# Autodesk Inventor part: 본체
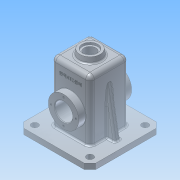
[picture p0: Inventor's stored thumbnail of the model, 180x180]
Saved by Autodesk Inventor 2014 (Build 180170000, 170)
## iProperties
Created: 2016-02
Part Number: 본체
Material: 알루미늄 6061
Document SubType Name: Modeling
Designer: net
Density: 2.71 g/cm^3
Appearance: 알루미늄 - 평지
Mass: 932.811 g
Surface Area: 1043.48 cm^2
Volume: 344.211 cm^3
Author: net
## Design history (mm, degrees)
sketch "스케치1"
  geometry: C1 r 27.5 at (0, 0); 1 further point
  constraints: 1 centre point, 1 coincident
  dimensions: "d0" = 55 diameter of C1
extrude "돌출1" new body sketch "스케치1" stored distance "d1" = 96; taper "d2" = 0 deg
sketch "스케치2"
  geometry: L1 (-35, 65)-(35, 65); L2 (35, 65)-(35, -55); L3 (35, -55)-(-35, -55); L4 (-35, -55)-(-35, 65); 2 further points
  constraints: 8 end point, 2 parallel, 1 horizontal, 1 midpoint, 1 perpendicular, 1 vertical alignment
  dimensions: "d3" = 70 distance of L1.start L1.end; "d4" = 120 distance of L1.end L2.end; "d5" = 55 distance from line of point (0, 0) L3
extrude "돌출2" join sketch "스케치2" stored distance "d6" = 70; taper "d7" = 0 deg
sketch "스케치3"
  geometry: L1 (-30, 30)-(100, 30); L2 (100, 30)-(100, -100); L3 (100, -100)-(-30, -100); L4 (-30, -100)-(-30, 30); 3 further points
  constraints: 8 end point, 2 midpoint, 2 parallel, 1 horizontal, 1 horizontal alignment, 1 perpendicular, 1 vertical alignment
  dimensions: "d8" = 130 distance of L1.start L1.end; "d9" = 130 distance of L1.end L2.end
extrude "돌출3" join sketch "스케치3" distance "d10" = 10; taper "d11" = 0 deg
sketch "스케치5"
  geometry: L1 (-35, 65)-(35, 65) reference; L2 (65, -55)-(-65, -55) reference; L3 (-35, -45)-(-35, 65) reference; L4 (35, 65)-(35, -45) reference; L5 (-30, 60)-(30, 60); L6 (30, 60)-(30, -55); L7 (-30, -55)-(-30, 60); 1 further point
  constraints: 6 end point, 3 parallel, 2 point on line
  dimensions: "d12" = 5 distance between parallel lines of L4 L6; "d13" = 5 distance between parallel lines of L1 L5; "d14" = 5 distance between parallel lines of L3 L7
extrude "돌출4" cut sketch "스케치5" stored distance "d15" = 60; taper "d16" = 0 deg
sketch "스케치6"
  geometry: L1 (-30, 60)-(-30, -55) reference; L2 (0, 0)-(-30, 0); L3 (-30, 27.5)-(-23, 20.5); L4 (-23, 20.5)-(-23, 0); L5 (-35, 65)-(-35, -45) reference
  constraints: 6 end point, 3 point on line, 2 perpendicular
  dimensions: "d17" = 135 deg angle of L3 L4; "d18" = 12 distance between parallel lines of L5 L4; "d19" = 55 diameter of L3.start L2
revolve "회전1" sketch "스케치6" stored, may be unused: angle "d20" = 90 deg
sketch "스케치7"
  geometry: C1 r 20.5 at (0, 0) reference; C2 r 16 at (0, 0)
  constraints: 1 centre point, 1 coincident
  dimensions: "d21" = 32 diameter of C2
extrude "돌출5" cut sketch "스케치7" stored distance "d22" = 60; taper "d23" = 0 deg
sketch "스케치8" dims "d24" = 45
  geometry: C1 r 16 at (0, 0) reference; C2 r 27.5 at (0, 0) reference; 2 further points
  constraints: 2 vertical alignment, 1 coincident, 2 other
hole "구멍1" sketch "스케치8" at (0, 22.5) diameter "d25" = 3.242; stored, may be unused: countersink angle "d29" = 90 deg, drill point angle "d31" = 118 deg; dims "d26" = 8, "d27" = 4, "d28" = 2, "d30" = 10
sketch "스케치9" dims "d35" = 45
  geometry: C1 r 16 at (0, 0) reference; C2 r 27.5 at (0, 0) reference; 2 further points
  constraints: 2 vertical alignment, 1 coincident, 2 other
hole "구멍2" sketch "스케치9" at (0, -22.5) diameter "d36" = 3.242; stored, may be unused: countersink angle "d40" = 90 deg, drill point angle "d42" = 118 deg; dims "d37" = 8, "d38" = 4, "d39" = 2, "d41" = 10
chamfer "모따기1" distance "d46" = 10; stored, may be unused: second distance "d47" = 2, angle "d48" = 45 deg
sketch "스케치10"
  geometry: C1 r 20 at (35, -35); 1 further point
  constraints: 1 centre point, 1 coincident
  dimensions: "d49" = 40 diameter of C1
extrude "돌출6" join sketch "스케치10" distance "d50" = 10; taper "d51" = -10 deg
sketch "스케치15"
  geometry: L1 (-90, -100)-(20, -100) reference; L2 (30, -90)-(30, 20) reference; L3 (20, 30)-(-90, 30) reference; C1 r 6 at (-85, 15); C2 r 6 at (15, 15); C3 r 6 at (-85, -85); C4 r 6 at (15, -85); 1 further point
  constraints: 4 centre point, 3 equal radius, 2 horizontal alignment, 2 vertical alignment
  dimensions: "d58" = 12 diameter of C1; "d60" = 15 distance from line of C2.centre L2; "d61" = 100 distance of C1.centre C2.centre; "d62" = 15 distance from line of C2.centre L3; "d63" = 15 distance from line of C4.centre L1
extrude "돌출9" cut sketch "스케치15" stored distance "d64" = 4; taper "d65" = 0 deg
sketch "스케치16"
  geometry: L1 (-55, -45)-(55, -45) reference; L2 (35, 65)-(35, -45) reference; L3 (50, -45)-(35, 40.069); L4 (65, -45)-(65, -55) reference; 1 further point
  constraints: 2 end point, 2 point on line
  dimensions: "d66" = 10 deg angle of L4 L3; "d67" = 15 distance from line of L4 L3.start
extrude "돌출10" join sketch "스케치16" stored distance "d68" = 10; taper "d69" = 0 deg
sketch "스케치18"
  geometry: C1 r 18.237 at (0, 0) reference; C2 r 10.5 at (0, 0)
  constraints: 1 centre point, 1 coincident
  dimensions: "d70" = 21 diameter of C2
extrude "돌출11" cut sketch "스케치18" stored distance "d71" = 10; taper "d72" = 0 deg
sketch "스케치19"
  geometry: C1 r 10.5 at (0, 0) reference; C2 r 18.237 at (0, 0) reference; C3 r 14 at (0, 0)
  constraints: 1 centre point, 1 coincident
  dimensions: "d73" = 28 diameter of C3
extrude "돌출12" cut sketch "스케치19" distance "d74" = 4; taper "d75" = 0 deg
sketch "스케치20"
  geometry: L1 (35, -45)-(35, 65) reference; L2 (-18.237, 75)-(18.237, 75) reference; 1 further point
  constraints: 1 other
  dimensions: "d76" = 35 distance from line of point (0, 45) L1; "d77" = 30 distance from line of point (0, 45) L2
feature "엠보싱1" sketch "스케치20" dims "d0" = 55, "d10" = 10, "d11" = 0, "d78" = 0.5, "d79" = 0
fillet "모깎기1" dims "d80" = 3
fillet "모깎기2" dims "d81" = 3
fillet "모깎기3" dims "d82" = 3
fillet "모깎기4" dims "d83" = 8
fillet "모깎기5" dims "d84" = 8
chamfer "모따기2" distance "d87" = 1; stored, may be unused: second distance "d88" = 2, angle "d89" = 45 deg
fillet "모깎기8" dims "d90" = 0.5
fillet "모깎기9" dims "d91" = 0.5
sketch "스케치21"
  geometry: C1 r 20.5 at (0, 0) reference; C2 r 16 at (0, 0)
  constraints: 1 centre point, 1 coincident
  dimensions: "d92" = 32 diameter of C2
extrude "돌출13" cut sketch "스케치21" stored distance "d93" = 4; taper "d94" = 0 deg
fillet "모깎기10" dims "d95" = 0.5
fillet "모깎기11" dims "d96" = 0.5
fillet "모깎기13" dims "d98" = 3
fillet "모깎기14" dims "d99" = 3
fillet "모깎기15" dims "d100" = 3
fillet "모깎기16" dims "d101" = 3
node "솔리드1"
pattern_circular "원형 패턴1" dims angle "d33" = 360 deg
pattern_circular "원형 패턴2" dims angle "d44" = 360 deg
mirror "대칭1"
mirror "대칭2"
